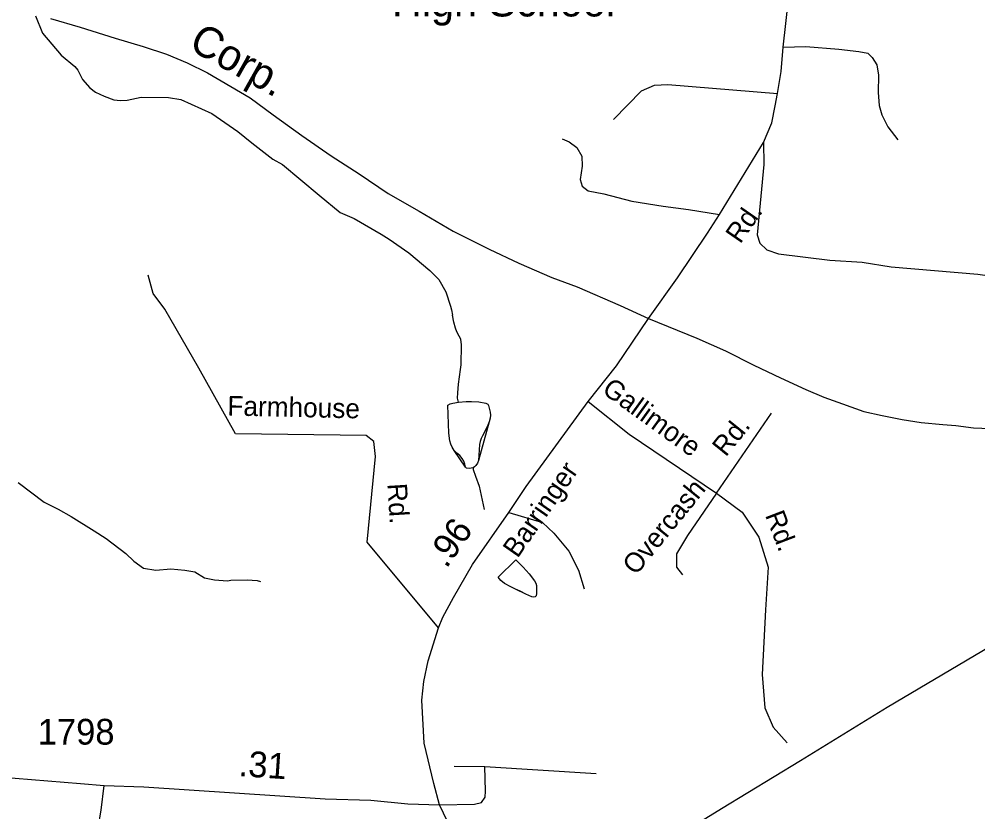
# Model space of a CAD drawing. Extents: x 1473865 to 1648260, y 639067 to 773536.
# Drawn here: x 1526150 to 1530800, y 714496 to 718342 of the extents above; entities that cross this region are included whole.
import ezdxf

# ---------------------------------------------------------------- set-up
doc = ezdxf.new("R2010")
doc.units = 0
for name, color, linetype in [('Exist Cultural Educational Facility High Label', 7, 'Continuous'), ('Exist Hydrographic Misc Water Feature', 7, 'Continuous'), ('Exist Railroad Mainline', 7, 'Continuous'), ('Exist Railroad Mainline Label', 7, 'Continuous'), ('Exist Road Non-System Type 51', 7, 'Continuous'), ('Exist Road Non-System Type 51 Label', 7, 'Continuous'), ('Exist Road Secondary Mileage Hundredths English Label', 7, 'Continuous'), ('Exist Road Secondary Type 51 Attributed', 7, 'Continuous'), ('Exist Road Secondary Type 51 Label', 7, 'Continuous'), ('Exist Road Secondary Type 51 Number Label', 7, 'Continuous'), ('Exist Utilities Electrical Transmission Line', 7, 'Continuous')]:
    doc.layers.add(name, color=color, linetype=linetype)

msp = doc.modelspace()

# ---------------------------------------------------------------- linework, layer by layer
at = {"layer": 'Exist Hydrographic Misc Water Feature'}
for points in [[(1526229.8, 718358.5), (1526264.2, 718273.8), (1526354.2, 718168), (1526421.1, 718112.6), (1526434.8, 718094.4), (1526457.9, 718050), (1526493.1, 718009.2), (1526520.7, 717988.7), (1526562.3, 717967.9), (1526610, 717950.9), (1526642, 717948.2), (1526674, 717949.6), (1526742.4, 717964.2), (1526875, 717962.9), (1526934.1, 717952.3), (1527084.9, 717885.3), (1527211.2, 717796.8), (1527278.1, 717741.4), (1527380.6, 717663.4), (1527428, 717636.4), (1527605.2, 717488.9), (1527707.6, 717404.9), (1527775.1, 717375.5), (1527905.6, 717298.9), (1527945.2, 717274.1), (1528039.9, 717208.2), (1528142.2, 717122.1), (1528185.4, 717079.3), (1528220.3, 717018.6), (1528242.9, 716950.2), (1528247.3, 716931.5), (1528251.8, 716906.6)], [(1528280.9, 716483.4), (1528276.1, 716502.7), (1528277.2, 716529.2), (1528280.7, 716571.2), (1528291.5, 716642.7), (1528294.1, 716665.5), (1528296.1, 716762.7), (1528292, 716788.8), (1528284, 716804.5), (1528273.1, 716825.6), (1528266.1, 716842.3), (1528258.9, 716872.6), (1528251.8, 716906.6)], [(1528351.6, 716165.2), (1528332.8, 716162.5), (1528319.9, 716163.9), (1528315.3, 716168.6), (1528312, 716182.7), (1528306.6, 716197.4), (1528299, 716210.1), (1528287.4, 716224.4), (1528272.6, 716236.1), (1528259.8, 716249.4), (1528249.8, 716264.7), (1528243.3, 716279.4), (1528238.9, 716296.1), (1528234, 716333.7), (1528228.6, 716469.5), (1528240.7, 716475.9), (1528253.2, 716478.8), (1528280.9, 716483.4)], [(1528351.6, 716165.2), (1528332.8, 716162.5), (1528319.9, 716163.9), (1528315.3, 716168.6), (1528259.8, 716249.4), (1528249.8, 716264.7), (1528243.3, 716279.4), (1528238.9, 716296.1), (1528234, 716333.7), (1528228.6, 716469.5), (1528240.7, 716475.9), (1528253.2, 716478.8), (1528280.9, 716483.4)], [(1528280.9, 716483.4), (1528317.9, 716486.7), (1528343.9, 716487.7), (1528379.2, 716484.8), (1528413.4, 716478.9), (1528422.7, 716474.5), (1528426.1, 716467.7), (1528435.4, 716435.3), (1528436.6, 716420.7), (1528434.8, 716406.7), (1528430.2, 716388.1), (1528419.3, 716363.9), (1528397.1, 716320.7), (1528391.1, 716307.8), (1528385.5, 716292.9), (1528382.2, 716278.4), (1528380, 716226.5), (1528377.3, 716200.5), (1528372.9, 716188.2), (1528365.4, 716175.9), (1528359, 716169.3), (1528351.6, 716165.2)], [(1528280.9, 716483.4), (1528317.9, 716486.7), (1528343.9, 716487.7), (1528379.2, 716484.8), (1528413.4, 716478.9), (1528422.7, 716474.5), (1528426.1, 716467.7), (1528435.4, 716435.3), (1528436.6, 716420.7), (1528434.8, 716406.7), (1528430.2, 716388.1), (1528377.3, 716200.5), (1528372.9, 716188.2), (1528365.4, 716175.9), (1528359, 716169.3), (1528351.6, 716165.2)], [(1528351.6, 716165.2), (1528351.5, 716156.3), (1528362.9, 716124.2), (1528381.9, 716075.8), (1528405.7, 715963.3)], [(1526145.8, 716093.2), (1526272, 715998.7), (1526339.3, 715965.3), (1526403.2, 715928.3), (1526513.3, 715859.8), (1526572.6, 715822.6), (1526667.2, 715748.8), (1526706.5, 715712), (1526753.8, 715679), (1526813.6, 715667.8), (1526885.2, 715675.6), (1526953.8, 715669), (1527001.5, 715660), (1527049, 715631.1), (1527096.9, 715622.1), (1527160.8, 715616.8), (1527176.9, 715620.4), (1527256.8, 715620.9), (1527304.8, 715617.9), (1527320.7, 715613.5)], [(1528559.8, 715718.4), (1528594.4, 715683.8), (1528624, 715651.4), (1528648.9, 715617), (1528656.6, 715605.4), (1528659.8, 715593.6), (1528659.3, 715555.3), (1528657.7, 715544), (1528653.4, 715539.5), (1528647.2, 715538), (1528636.2, 715539.6), (1528608.1, 715552.6), (1528580.1, 715567.4), (1528557.2, 715576.6), (1528534.9, 715587.1), (1528503.9, 715604), (1528486.6, 715619.2), (1528472.8, 715634.3), (1528559.8, 715718.4)], [(1528559.8, 715718.4), (1528594.4, 715683.8), (1528624, 715651.4), (1528648.9, 715617), (1528656.6, 715605.4), (1528659.8, 715593.6), (1528659.3, 715555.3), (1528657.7, 715544), (1528653.4, 715539.5), (1528647.2, 715538), (1528636.2, 715539.6), (1528608.1, 715552.6), (1528557.2, 715576.6), (1528534.9, 715587.1), (1528503.9, 715604), (1528486.6, 715619.2), (1528472.8, 715634.3), (1528559.8, 715718.4)]]:
    msp.add_lwpolyline(points, dxfattribs=at)
at = {"layer": 'Exist Railroad Mainline'}
msp.add_lwpolyline([(1526302.2, 718345.5), (1526445.6, 718303.2), (1526616.7, 718250.1), (1526752.1, 718209.8), (1526865.6, 718171.9), (1526964.8, 718130.1), (1527064.1, 718082.2), (1527177, 718016.3), (1527270.1, 717960.6), (1527382.7, 717878.7), (1527521.2, 717778.2), (1527663.5, 717679.7), (1527799.9, 717591.3), (1527940.5, 717496.8), (1528091, 717410.2), (1528255.6, 717313.4), (1528430.1, 717226.2), (1528573, 717157.7), (1528733.9, 717088.8), (1528856.3, 717044.1), (1529065.8, 716952.5), (1529203.3, 716889.7), (1529437, 716795.1), (1529576.1, 716733.4), (1529713.1, 716663.9), (1529842, 716601.4), (1529965.1, 716545.3), (1530052.6, 716507.7), (1530144, 716476.2), (1530247.5, 716438.3), (1530335.1, 716418.8), (1530433, 716399.2), (1530524.8, 716385.5), (1530630.6, 716375.8), (1530692.6, 716370.7), (1530778.4, 716359.2), (1530902.3, 716355.1)], dxfattribs=at)
at = {"layer": 'Exist Road Non-System Type 51'}
for p, q in [((1528260, 714718.3), (1528408.5, 714715.1)), ((1528408.5, 714715.1), (1528949.4, 714681.7))]:
    msp.add_line(p, q, dxfattribs=at)
for points in [[(1529855.2, 718206.6), (1529965.3, 718209.1), (1530125.1, 718196.9), (1530223, 718185.5), (1530266.8, 718176.8), (1530286.6, 718156.6), (1530310.1, 718120.3), (1530317.3, 718070.2), (1530316.2, 717986.1), (1530321.3, 717924), (1530334.8, 717877.7), (1530364, 717819.3), (1530411.2, 717756.7)], [(1529032.2, 717855.1), (1529168.9, 717993.9), (1529232.1, 718022.2), (1529297, 718025.4), (1529827.5, 717981)], [(1528783.3, 717761.2), (1528817, 717746.7), (1528854.7, 717720.3), (1528880, 717677.8), (1528881.5, 717629.7), (1528870.5, 717563.9), (1528880.1, 717531.7), (1528909.9, 717509.3), (1528985.8, 717494.3), (1529121.1, 717458.4), (1529272.9, 717434.3), (1529396.7, 717418.4), (1529547.1, 717394.9)], [(1529761, 717743.6), (1529761.7, 717637.6), (1529729, 717295.8), (1529742.5, 717255.5), (1529776.1, 717223), (1529833.8, 717204.3), (1530081.4, 717172.9), (1530239.3, 717162.7), (1530378.9, 717140.6), (1530800.4, 717104.7), (1530960.3, 717082.5)], [(1528184.7, 715388), (1527837.5, 715804.2), (1527877.9, 716220.3), (1527869.8, 716293.1), (1527833.5, 716321.3), (1527199.6, 716329.4), (1527022, 716648.6), (1526856.8, 716934.3), (1526800.2, 717011), (1526776, 717099.9)], [(1528910.7, 716486.8), (1529108.5, 716329.2), (1529532.4, 716042.3)], [(1529532.4, 716042.3), (1529798.9, 716430.2)], [(1529532.4, 716042.3), (1529391.1, 715836.3), (1529338.6, 715747.4), (1529338.6, 715682.7), (1529366.9, 715646.4)], [(1529532.4, 716042.3), (1529657.6, 715949.4), (1529738.3, 715828.2), (1529782.7, 715682.7), (1529770.6, 715476.7), (1529754.5, 715161.6), (1529766.6, 714999.9), (1529806.9, 714907), (1529875.6, 714830.3)], [(1528525.1, 715947.6), (1528688.4, 715899.3), (1528743.6, 715848.6), (1528816.5, 715761.5), (1528863.3, 715668.9), (1528890, 715578.5)], [(1528189.7, 714529.3), (1528358.8, 714533), (1528393, 714541.6), (1528410.1, 714566.5), (1528411.7, 714596.8), (1528408.5, 714715.1)]]:
    msp.add_lwpolyline(points, dxfattribs=at)
at = {"layer": 'Exist Road Secondary Type 51 Attributed'}
for points in [[(1529203.3, 716889.7), (1529342.7, 717087), (1529489, 717304.1), (1529547.1, 717394.9), (1529761, 717743.6), (1529800.4, 717839.1), (1529817.4, 717921), (1529827.5, 717981), (1529845.6, 718088.7), (1529855.2, 718206.6), (1529898.3, 718581.1), (1529929.7, 718871), (1529955.8, 719056.4)], [(1528189.7, 714529.3), (1528161.4, 714633.9), (1528114.1, 714828.8), (1528102.9, 715037.1), (1528112.2, 715129), (1528133.4, 715228.8), (1528184.7, 715388), (1528204.9, 715440.6), (1528257.5, 715535.2), (1528349.7, 715696.1), (1528525.1, 715947.6), (1528608.7, 716074.6), (1528910.7, 716486.8), (1529047.6, 716660.5), (1529203.3, 716889.7)], [(1524919.1, 713952.4), (1524941.9, 714019.3), (1524972.2, 714152.5), (1524998.3, 714239), (1525028.5, 714342), (1525062.8, 714396.9), (1525110.9, 714450.5), (1525342.9, 714630.4), (1525421.2, 714686.7), (1525463.8, 714707.3), (1525511.9, 714714.2), (1525550.3, 714716.9), (1525747.5, 714694.1), (1526050.9, 714666.1), (1526447.3, 714632.8), (1526563, 714623.8)], [(1526519.2, 714336.4), (1526547.4, 714504.1), (1526563, 714623.8)], [(1526563, 714623.8), (1526755, 714617.1), (1527634, 714559), (1527856, 714551.9), (1528035.8, 714535.4), (1528189.7, 714529.3)], [(1530550.5, 708434), (1530525, 708537), (1530246.3, 709445.8), (1530019.9, 710165.3), (1529973.7, 710318.1), (1529903.3, 710573.3), (1529816.6, 710828.6), (1529761.1, 711015.4), (1529649.8, 711369.2), (1529566.6, 711566.6), (1529467.3, 711776.1), (1529370.2, 711991.6), (1529177.6, 712398.5), (1529067, 712648.2), (1528948.2, 712891.9), (1528841.4, 713131.6), (1528742, 713333.1), (1528658.5, 713516.3), (1528457.1, 713962.5), (1528370.9, 714143), (1528291.3, 714310.1), (1528249.5, 714405), (1528189.7, 714529.3)]]:
    msp.add_lwpolyline(points, dxfattribs=at)
at = {"layer": 'Exist Utilities Electrical Transmission Line'}
msp.add_lwpolyline([(1531191.7, 715494.4), (1530783.6, 715253.3), (1530359.3, 715002.3), (1529938.9, 714743.5), (1529556.8, 714509.9), (1529122.2, 714241.3), (1528748.6, 714023.5), (1528502, 713881.9), (1528099.7, 713630.6), (1527531.7, 713276.1), (1527010.1, 712954.9), (1526589.6, 712692), (1526061.7, 712344.9), (1525022.6, 711690.6), (1524579.9, 711422), (1524118.9, 711135.7), (1523815.1, 710942)], dxfattribs=at)

# ---------------------------------------------------------------- texts
at = {"layer": 'Exist Cultural Educational Facility High Label'}
msp.add_text('High School', height=150, rotation=0, dxfattribs=at).set_placement((1527958.2, 718355.4))
at = {"layer": 'Exist Railroad Mainline Label'}
msp.add_text('Corp.', height=150, rotation=330.6546, dxfattribs=at).set_placement((1526966, 718200.5))
at = {"layer": 'Exist Road Non-System Type 51 Label'}
for s, rotation, p in [('Gallimore', 324.1763, (1528971.7, 716532.2)), ('Farmhouse', 358.6993, (1527159.6, 716419.4)), ('Rd.', 51.021, (1529577.1, 716214.7)), ('Rd.', 273.5955, (1527935.8, 716087.6)), ('Overcash', 50.8691, (1529141.8, 715639.6)), ('Rd.', 290.9822, (1529767.1, 715935.8))]:
    msp.add_text(s, height=95, rotation=rotation, dxfattribs=at).set_placement(p)
at = {"layer": 'Exist Road Secondary Mileage Hundredths English Label'}
for s, rotation, p in [('.96', 55.1217, (1528222.4, 715673.1)), ('.31', 356.214, (1527212.4, 714669.5))]:
    msp.add_text(s, height=125, rotation=rotation, dxfattribs=at).set_placement(p)
at = {"layer": 'Exist Road Secondary Type 51 Label'}
for s, rotation, p in [('Rd.', 55.2431, (1529647.5, 717248.2)), ('Barringer', 55.1409, (1528567.4, 715723.1))]:
    msp.add_text(s, height=95, rotation=rotation, dxfattribs=at).set_placement(p)
at = {"layer": 'Exist Road Secondary Type 51 Number Label'}
msp.add_text('1798', height=125, dxfattribs=at).set_placement((1526240.8, 714822.1))

doc.saveas('drawing.dxf')
